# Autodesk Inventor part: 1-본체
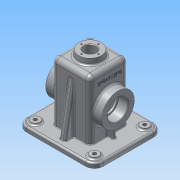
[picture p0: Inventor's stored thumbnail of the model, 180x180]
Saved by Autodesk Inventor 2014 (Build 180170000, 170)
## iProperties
Created: 2015-12
Part Number: 1-본체
Material: 알루미늄 6061
Document SubType Name: Modeling
Designer: Administrator
Density: 2.71 g/cm^3
Appearance: 알루미늄 - 평지
Mass: 860.643 g
Surface Area: 908.789 cm^2
Volume: 317.581 cm^3
Author: Administrator
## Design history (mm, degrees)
sketch "스케치1"
  geometry: L1 (-50, 52.5)-(50, 52.5); L2 (60, 42.5)-(60, -42.5); L3 (50, -52.5)-(-50, -52.5); L4 (-60, -42.5)-(-60, 42.5); A1 r 10 centre (-50, 42.5) between (-50, 52.5) and (-60, 42.5); A2 r 10 centre (50, 42.5) between (60, 42.5) and (50, 52.5); A3 r 10 centre (50, -42.5) between (50, -52.5) and (60, -42.5); A4 r 10 centre (-50, -42.5) between (-60, -42.5) and (-50, -52.5); 6 further points
  constraints: 8 end point, 8 point on circle, 8 tangent, 6 point on line, 4 centre point, 3 equal radius, 2 midpoint, 2 parallel, 1 horizontal, 1 horizontal alignment, 1 perpendicular, 1 vertical alignment
  dimensions: "d0" = 120 distance of point (-60, 52.5) point (60, 52.5); "d1" = 105 distance of point (60, 52.5) point (60, -52.5); "d2" = 10 radius of A1
extrude "돌출1" new body sketch "스케치1" distance "d3" = 2; taper "d4" = 0 deg
sketch "스케치2"
  geometry: L1 (-50, 57.5)-(50, 57.5); L2 (65, 42.5)-(65, -42.5); L3 (50, -57.5)-(-50, -57.5); L4 (-65, -42.5)-(-65, 42.5); A1 r 15 centre (-50, 42.5) between (-50, 57.5) and (-65, 42.5); A2 r 15 centre (50, 42.5) between (65, 42.5) and (50, 57.5); A3 r 15 centre (50, -42.5) between (50, -57.5) and (65, -42.5); A4 r 15 centre (-50, -42.5) between (-65, -42.5) and (-50, -57.5); 6 further points
  constraints: 8 end point, 8 point on circle, 8 tangent, 6 point on line, 4 centre point, 3 equal radius, 2 midpoint, 2 parallel, 1 horizontal, 1 horizontal alignment, 1 perpendicular, 1 vertical alignment
  dimensions: "d5" = 115 distance of point (65, 57.5) point (65, -57.5); "d6" = 130 distance of point (-65, 57.5) point (65, 57.5); "d7" = 15 radius of A1
extrude "돌출2" join sketch "스케치2" distance "d8" = 8; taper "d9" = 0 deg
sketch "스케치3"
  geometry: C1 r 7.5 at (-50, 42.5); C2 r 7.5 at (50, 42.5); C3 r 7.5 at (-50, -42.5); C4 r 7.5 at (50, -42.5); C5 r 3 at (-50, 42.5); C6 r 3 at (50, 42.5); C7 r 3 at (50, -42.5); C8 r 3 at (-50, -42.5); A1 r 15 centre (-50, 42.5) between (-50, 57.5) and (-65, 42.5) reference; A2 r 15 centre (-50, -42.5) between (-65, -42.5) and (-50, -57.5) reference; A3 r 15 centre (50, -42.5) between (50, -57.5) and (65, -42.5) reference; A4 r 15 centre (50, 42.5) between (65, 42.5) and (50, 57.5) reference; 1 further point
  constraints: 8 centre point, 8 coincident, 6 equal radius
  dimensions: "d10" = 15 diameter of C1; "d13" = 6 diameter of C5
extrude "돌출3" join sketch "스케치3" distance "d11" = 3; taper "d12" = 0 deg
extrude "돌출4" cut sketch "스케치3" stored distance "d14" = 3; taper "d15" = 0 deg
sketch "스케치4"
  geometry: L1 (-32.5, 110)-(32.5, 110); L2 (32.5, 110)-(32.5, 0); L3 (32.5, 0)-(-32.5, 0); L4 (-32.5, 0)-(-32.5, 110); 2 further points
  constraints: 8 end point, 2 coincident, 2 parallel, 1 horizontal, 1 midpoint, 1 perpendicular
  dimensions: "d16" = 110 distance between parallel lines of L3 L1; "d17" = 65 distance of L1.start L1.end
extrude "돌출5" join sketch "스케치4" stored distance "d18" = 65; taper "d19" = 0 deg
sketch "스케치5"
  geometry: C1 r 20 at (32.5, 32.5); 1 further point
  constraints: 1 centre point, 1 coincident
  dimensions: "d20" = 40 diameter of C1
extrude "돌출6" join sketch "스케치5" distance "d21" = 10; taper "d22" = -5 deg
fillet "모깎기1" dims "d23" = 8
sketch "스케치6"
  geometry: L1 (-52.5, 2)-(-57.5, 2) reference; L2 (-57.5, 2)-(-57.5, 10) reference; L3 (-57.5, 10)-(-32.5, 10) reference; L4 (-32.5, 10)-(-32.5, 102) reference; L5 (-24.5, 110)-(-20, 110) reference; L6 (-20, 110)-(-19.125, 120) reference; L7 (-19.125, 120)-(19.125, 120) reference; L8 (19.125, 120)-(20, 110) reference; L9 (20, 110)-(24.5, 110) reference; L10 (32.5, 102)-(32.5, 10) reference; L11 (32.5, 10)-(57.5, 10) reference; L12 (57.5, 10)-(57.5, 2) reference; L13 (57.5, 2)-(52.5, 2) reference; L14 (52.5, 2)-(52.5, 0) reference; L15 (52.5, 0)-(-52.5, 0) reference; L16 (-52.5, 0)-(-52.5, 2) reference; L17 (-32.5, 95.069)-(-47.5, 10); L18 (32.5, 95.069)-(47.5, 10); C1 r 27.5 at (0, 55); A1 r 8 centre (-24.5, 102) between (-24.5, 110) and (-32.5, 102) reference; A2 r 8 centre (24.5, 102) between (32.5, 102) and (24.5, 110) reference; 2 further points
  constraints: 4 end point, 4 point on line, 1 centre point, 1 equal length, 1 midpoint, 1 vertical alignment
  dimensions: "d24" = 55 distance from line of L15 C1.centre; "d25" = 55 diameter of C1; "d28" = 10 distance from line of L17.end L2; "d29" = 10 deg angle of L17 L2; "d30" = 10 deg angle of L18 L12
  node "절단 모서리 투영1"
extrude "돌출7" join sketch "스케치6" stored distance "d26" = 95; taper "d27" = 0 deg
extrude "돌출8" join sketch "스케치6" stored distance "d31" = 10; taper "d32" = 0 deg
sketch "스케치7"
  geometry: L1 (-27.5, 105)-(27.5, 105); L2 (27.5, 105)-(27.5, 0); L3 (27.5, 0)-(-27.5, 0); L4 (-27.5, 0)-(-27.5, 105); L5 (-32.5, 67.49)-(-32.5, 102) reference; L6 (-24.5, 110)-(24.5, 110) reference; L7 (-60, 2)-(-65, 2) reference; L8 (-65, 2)-(-65, 10) reference; L9 (-65, 10)-(-32.5, 10) reference; L10 (-32.5, 10)-(-32.5, 27.5) reference; L11 (-32.5, 27.5)-(-47.5, 27.5) reference; L12 (-47.5, 27.5)-(-47.5, 82.5) reference; L13 (-47.5, 82.5)-(-32.5, 82.5) reference; L14 (-32.5, 82.5)-(-32.5, 102) reference; L15 (-24.5, 110)-(-20, 110) reference; L16 (-20, 110)-(-19.125, 120) reference; L17 (-19.125, 120)-(19.125, 120) reference; L18 (19.125, 120)-(20, 110) reference; L19 (20, 110)-(24.5, 110) reference; L20 (32.5, 102)-(32.5, 82.5) reference; L21 (32.5, 82.5)-(47.5, 82.5) reference; L22 (47.5, 82.5)-(47.5, 27.5) reference; L23 (47.5, 27.5)-(32.5, 27.5) reference; L24 (32.5, 27.5)-(32.5, 10) reference; L25 (32.5, 10)-(65, 10) reference; L26 (65, 10)-(65, 2) reference; L27 (65, 2)-(60, 2) reference; L28 (60, 2)-(60, 0) reference; L29 (60, 0)-(-60, 0) reference; L30 (-60, 0)-(-60, 2) reference; L31 (42.5, 36.604)-(42.5, 10); L32 (42.5, 10)-(32.5, 10); L33 (32.5, 10)-(32.5, 36.604); L34 (32.5, 36.604)-(42.5, 36.604); L35 (-42.5, 36.604)-(-32.5, 36.604); L36 (-32.5, 36.604)-(-32.5, 10); L37 (-32.5, 10)-(-42.5, 10); L38 (-42.5, 10)-(-42.5, 36.604); A1 r 8 centre (-24.5, 102) between (-24.5, 110) and (-32.5, 102) reference; A2 r 8 centre (24.5, 102) between (32.5, 102) and (24.5, 110) reference; 10 further points
  constraints: 24 end point, 9 midpoint, 6 parallel, 3 perpendicular, 2 equal length, 2 horizontal, 2 horizontal alignment, 2 vertical alignment, 1 coincident
  dimensions: "d33" = 5 distance between parallel lines of L5 L4; "d34" = 5 distance between parallel lines of L6 L1; "d38" = 15 distance between parallel lines of L2 L31; "d39" = 26.60359 distance between parallel lines of L32 L34
  node "절단 모서리 투영2"
extrude "돌출9" cut sketch "스케치7" stored distance "d35" = 55; taper "d36" = 0 deg
extrude "돌출10" join sketch "스케치7" stored distance "d40" = 6; taper "d41" = 0 deg
hole "구멍1" diameter "d44" = 20; stored, may be unused: countersink angle "d48" = 90 deg, drill point angle "d50" = 118 deg; dims "d42" = 10, "d43" = 10, "d45" = 6, "d46" = 4, "d47" = 2, "d49" = 8
sketch "스케치8"
  geometry: C1 r 10 at (0, 0) reference; 1 further point
  constraints: 1 vertical alignment
  dimensions: "d51" = 14.5 distance of point (0, 14.5) C1.centre
hole "구멍2" sketch "스케치8" at (0, 14.5) diameter "d52" = 2.459; stored, may be unused: countersink angle "d56" = 90 deg, drill point angle "d58" = 118 deg; dims "d53" = 7, "d54" = 4, "d55" = 2, "d57" = 9
sketch "스케치9"
  geometry: C1 r 27.5 at (0, 0) reference; 2 further points
  constraints: 1 vertical alignment
  dimensions: "d62" = 21 distance of C1.centre point (0, 21)
hole "구멍3" sketch "스케치9" at (0, 21) diameter "d63" = 3.242; stored, may be unused: countersink angle "d67" = 90 deg, drill point angle "d69" = 118 deg; dims "d64" = 8, "d65" = 4, "d66" = 2, "d68" = 10
hole "구멍4" diameter "d75" = 30; stored, may be unused: countersink angle "d79" = 90 deg, drill point angle "d81" = 0 deg; dims "d73" = 10, "d74" = 10, "d76" = 8, "d77" = 35, "d78" = 17, "d80" = 10
chamfer "모따기1" distance "d82" = 1; stored, may be unused: second distance "d83" = 2, angle "d84" = 45 deg
sketch "스케치10"
  geometry: L1 (-120, -19.125)-(-120, 19.125) reference; A1 r 27.5 centre (-55, 0) between (-67.49, 24.5) and (-67.49, -24.5) reference; 2 further points
  constraints: 1 horizontal alignment, 1 other
  dimensions: "d85" = 26 distance from line of point (-94, 0) L1
feature "엠보싱1" sketch "스케치10" dims "d0" = 120, "d1" = 105, "d2" = 10, "d5" = 115, "d6" = 130, "d7" = 15, "d86" = 0.5, "d87" = 0
fillet "모깎기2" dims "d88" = 0.3, "d89" = 3
fillet "모깎기3" dims "d90" = 3
fillet "모깎기4" dims "d91" = 3
fillet "모깎기5" dims "d92" = 1
node "솔리드1"
pattern_circular "원형 패턴1" dims angle "d60" = 360 deg
pattern_circular "원형 패턴2" dims angle "d71" = 360 deg
mirror "대칭1"
